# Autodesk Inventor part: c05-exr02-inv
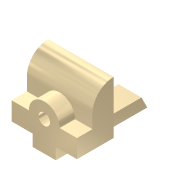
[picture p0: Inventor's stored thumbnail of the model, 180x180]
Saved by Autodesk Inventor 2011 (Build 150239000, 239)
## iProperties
Shininess: 65.0
Length Units: 11269
Angle Units: 11279
Time Units: 11290
Mass Units: 11283
Length Display Precision: 3
Angle Display Precision: 2
Created: 2001-11
Part Number: c05-exr02-inv
Document SubType Name: Modeling
Designer: Renu Muthoo
Density: 1 g/cm^3
Density: 0.0
Volumn: 0.0
Area: 0.0
PropertySet Name: Model Information
Control State: 0
Master: False
Checked Out: False
Author: Renu Muthoo
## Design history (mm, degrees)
node "Sketch1"
sketch "Sketch2"
  geometry: L1 (-68, 4)-(-68, -8); L2 (-68, -8)-(27, -8); L3 (27, -8)-(21, 4); L4 (21, 4)-(-68, 4)
  constraints: 8 end point, 1 horizontal, 1 perpendicular, 1 vertical
  dimensions: "d0" = 95 distance of L1.end L2.end; "d1" = 6 horizontal distance of L2.end L3.end; "d2" = 12 vertical distance of L2.end L3.end
extrude "Extrusion1" new body sketch "Sketch2" stored distance "d3" = 24; taper "d4" = 0 deg
sketch "Sketch3"
  geometry: L1 (-68, 4)-(-30, 4); L2 (-30, 4)-(-30, 59); L3 (-52, 37)-(-52, 23); L4 (-52, 23)-(-68, 23); L5 (-68, 23)-(-68, 4); L6 (-68, 4)-(21, 4) reference; L7 (-68, -8)-(-68, 4) reference; A1 r 22 centre (-30, 37) between (-30, 59) and (-52, 37)
  constraints: 10 end point, 3 parallel, 2 collinear, 2 point on circle, 1 centre point, 1 horizontal, 1 perpendicular, 1 point on line, 1 tangent
  dimensions: "d5" = 55 distance of L1.end L2.end; "d6" = 38 distance of L1.start L1.end; "d7" = 22 distance between parallel lines of L2 L3; "d8" = 19 distance of L4.end L1.start
extrude "Extrusion2" join sketch "Sketch3" stored distance "d9" = 68; taper "d10" = 0 deg
sketch "Sketch4"
  geometry: L1 (-4, 31)-(28, 31); L2 (-22, 31)-(46, 31) reference; L3 (46, 12)-(46, 31) reference; A1 r 16 centre (12, 31) between (28, 31) and (-4, 31)
  constraints: 2 end point, 2 point on circle, 1 centre point, 1 collinear, 1 horizontal
  dimensions: "d11" = 16 radius of A1; "d12" = 34 distance from line of L3 A1.centre
extrude "Extrusion3" join sketch "Sketch4" stored distance "d13" = 58; taper "d14" = 0 deg
sketch "Sketch5"
  geometry: C1 r 6 at (12, 31); 1 further point
  constraints: 1 centre point, 1 coincident
  dimensions: "d15" = 12 diameter of C1
extrude "Extrusion4" cut sketch "Sketch5" distance "d16" = 16; taper "d17" = 0 deg
body "Solid1"
